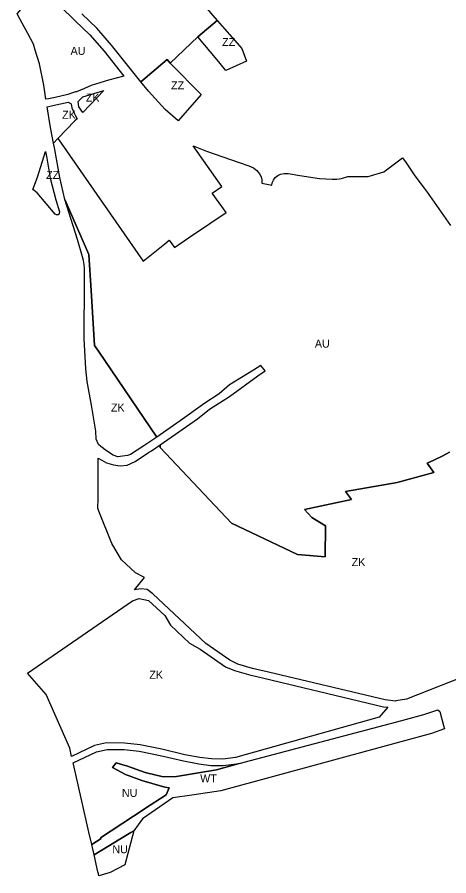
# Model space of a CAD drawing. Extents: x -535894 to -532834, y -1165802 to -1163647.
# Drawn here: x -535156 to -534886, y -1165663 to -1165127 of the extents above; entities that cross this region are included whole.
import ezdxf

# ---------------------------------------------------------------- set-up
doc = ezdxf.new("R2010")
doc.units = 0
for name, color, linetype in [('Vrstva 10', 7, 'Continuous'), ('Vrstva 16', 7, 'Continuous'), ('Vrstva 19', 7, 'Continuous'), ('Vrstva 22', 7, 'Continuous'), ('Vrstva 4', 7, 'Continuous')]:
    doc.layers.add(name, color=color, linetype=linetype)

msp = doc.modelspace()

# ---------------------------------------------------------------- linework, layer by layer
at = {"layer": 'Vrstva 10'}
for points in [[(-535030.794, -1165128.551), (-535016.81, -1165144.52), (-535015.48, -1165146.04), (-535012.56, -1165153.94), (-535025.48, -1165159.77), (-535026.15, -1165158.85), (-535030.91, -1165153.2), (-535042.84, -1165138.9)], [(-535078.389, -1165167.024), (-535062.12, -1165153.01), (-535060.13, -1165155.29), (-535059.81, -1165155.66), (-535040.74, -1165174.89), (-535055.086, -1165191.249), (-535063.193, -1165184.14), (-535073.739, -1165172.685)], [(-535145.859, -1165234.181), (-535143.033, -1165226.447), (-535137.971, -1165210.486), (-535137.13, -1165214.5), (-535134.967, -1165227.138), (-535131.592, -1165240.499), (-535129.335, -1165248.149), (-535129.389, -1165249.15), (-535130.061, -1165249.893), (-535131.052, -1165250.047), (-535131.919, -1165249.542), (-535143.165, -1165236.25)]]:
    msp.add_lwpolyline(points, close=True, dxfattribs=at)
at = {"layer": 'Vrstva 16'}
for points in [[(-535114.67, -1165186.14), (-535117.077, -1165182.508), (-535117.507, -1165179.149), (-535114.59, -1165176.22), (-535101.55, -1165172.42)], [(-535118.3, -1165189.93), (-535119.57, -1165191.26), (-535130.24, -1165202.4), (-535132.906, -1165205.189), (-535134.644, -1165196.443), (-535135.082, -1165194.239), (-535136.921, -1165182.604), (-535133.443, -1165181.633), (-535123.795, -1165179.535), (-535121.98, -1165180.725), (-535121.499, -1165183.162), (-535119.975, -1165186.84), (-535119.491, -1165187.733)], [(-535125.87, -1165240.38), (-535110.91, -1165274.78), (-535109.49, -1165297.17), (-535107.33, -1165331.56), (-535104.88, -1165335.18), (-535068.421, -1165388.794), (-535076.515, -1165394.257), (-535084.898, -1165399.647), (-535086.711, -1165400.218), (-535089.815, -1165400.622), (-535092.83, -1165401.015), (-535095.698, -1165400.055), (-535099.891, -1165397.3), (-535103.387, -1165394.572), (-535104.973, -1165393.334), (-535106.384, -1165390.083), (-535106.611, -1165385.025), (-535109.318, -1165368.871), (-535111.891, -1165354.083), (-535112.849, -1165346.141), (-535113.849, -1165327.11), (-535113.63, -1165291.112), (-535113.598, -1165285.864), (-535113.669, -1165283.44), (-535113.917, -1165280.968), (-535114.34, -1165278.52), (-535114.922, -1165276.165), (-535117.999, -1165265.365)], [(-535149.25, -1165536.15), (-535083.65, -1165491.01), (-535079.48, -1165489.46), (-535073.7, -1165490.85), (-535063.55, -1165500.03), (-535059.98, -1165506.16), (-535048.04, -1165517.37), (-535041.43, -1165521.13), (-535025.58, -1165532.21), (-535020.09, -1165534.38), (-535009.77, -1165537.3), (-535006.933, -1165537.976), (-534926.87, -1165557.06), (-534924.332, -1165557.424), (-534929.63, -1165563.61), (-535019.35, -1165588.86), (-535027.27, -1165589.76), (-535034.45, -1165589.68), (-535041.62, -1165588.86), (-535051.02, -1165587.04), (-535065.45, -1165583.66), (-535078.98, -1165580.85), (-535088.71, -1165579.86), (-535099.93, -1165579.7), (-535107.35, -1165581.35), (-535121.655, -1165588.062), (-535122.82, -1165582.96), (-535137.55, -1165549.48)]]:
    msp.add_lwpolyline(points, close=True, dxfattribs=at)
msp.add_lwpolyline([(-534877.24, -1165538.36), (-534912.68, -1165552.42), (-534919.2, -1165553.5), (-534919.44, -1165553.53), (-534926.03, -1165552.84), (-534998.84, -1165535.55), (-535008.78, -1165533.19), (-535017.91, -1165530.5), (-535022.95, -1165527.99), (-535037.98, -1165517.6), (-535070.93, -1165486.65), (-535074.543, -1165483.89), (-535078.527, -1165483.386), (-535082.4, -1165484.03), (-535076.26, -1165476.34), (-535081.822, -1165473.417), (-535090.626, -1165465.393), (-535096.666, -1165455.119), (-535104.637, -1165435.067), (-535105.398, -1165433.153), (-535105.08, -1165427.18), (-535105, -1165401.823), (-535102.855, -1165403.084), (-535099.848, -1165404.852), (-535095.444, -1165405.995), (-535091.323, -1165406.681), (-535087.093, -1165406.349), (-535081.996, -1165403.907), (-535073.648, -1165398.418), (-535071.799, -1165397.236), (-535066.459, -1165393.597), (-535066.38, -1165395.21), (-535021.86, -1165442.54), (-534980.62, -1165462.08), (-534963.38, -1165463.4), (-534963.24, -1165444.04), (-534971.78, -1165438.88), (-534976.33, -1165433.85), (-534946.88, -1165427.7), (-534950.64, -1165422.73), (-534918.48, -1165416.99), (-534895.63, -1165410.85), (-534899.67, -1165405.03), (-534895.49, -1165403.09), (-534889.94, -1165400.51), (-534885.71, -1165398.12)], dxfattribs=at)
at = {"layer": 'Vrstva 19'}
for points in [[(-535103.18, -1165639.32), (-535109.1, -1165643.08), (-535110.85, -1165635.43), (-535120.55, -1165592.9), (-535120.744, -1165592.052), (-535106.051, -1165585.159), (-535099.519, -1165583.706), (-535088.941, -1165583.857), (-535079.591, -1165584.808), (-535066.313, -1165587.566), (-535051.857, -1165590.952), (-535042.228, -1165592.817), (-535034.7, -1165593.677), (-535027.066, -1165593.763), (-535017.005, -1165592.619), (-535031.28, -1165596.42), (-535056.11, -1165600.58), (-535064.42, -1165600.94), (-535075.77, -1165598.23), (-535086.71, -1165594.09), (-535093.94, -1165592.1), (-535096.22, -1165595.01), (-535088.09, -1165599.33), (-535077.76, -1165603.24), (-535063.44, -1165607.34), (-535060.83, -1165607.77), (-535062.6, -1165612.04), (-535076.16, -1165620.93), (-535076.36, -1165621.07), (-535103.74, -1165639.03)], [(-535082.82, -1165634.47), (-535088.47, -1165655.7), (-535097.63, -1165660.52), (-535104.63, -1165662.66), (-535104.92, -1165661.39), (-535105.21, -1165660.12), (-535107.61, -1165649.63), (-535086.73, -1165636.86), (-535084.78, -1165635.66)]]:
    msp.add_lwpolyline(points, close=True, dxfattribs=at)
at = {"layer": 'Vrstva 22'}
msp.add_lwpolyline([(-535141.331, -1165107.067), (-535128.931, -1165119.482), (-535119.396, -1165128.806), (-535110.216, -1165137.551), (-535101.402, -1165147.865), (-535089.002, -1165163.415), (-535098.68, -1165165.83), (-535109.532, -1165169.282), (-535113.551, -1165171.039), (-535118.727, -1165173.09), (-535119.161, -1165173.236), (-535120.442, -1165173.67), (-535124.139, -1165174.765), (-535131.907, -1165176.691), (-535136.049, -1165177.441), (-535137.699, -1165177.679), (-535139.073, -1165168.99), (-535141.761, -1165155.672), (-535144.388, -1165147.195), (-535145.543, -1165143.469), (-535148.99, -1165136.793), (-535152.58, -1165130.217), (-535155.665, -1165124.565), (-535141.94, -1165107.81)], close=True, dxfattribs=at)
for points in [[(-535041.39, -1165116.45), (-535030.794, -1165128.551), (-535042.84, -1165138.9), (-535060.13, -1165155.29), (-535062.12, -1165153.01), (-535078.389, -1165167.024), (-535096.773, -1165144.045), (-535105.854, -1165133.419), (-535115.229, -1165124.489)], [(-534885.71, -1165398.12), (-534889.94, -1165400.51), (-534895.49, -1165403.09), (-534899.67, -1165405.03), (-534895.63, -1165410.85), (-534918.48, -1165416.99), (-534950.64, -1165422.73), (-534946.88, -1165427.7), (-534976.33, -1165433.85), (-534971.78, -1165438.88), (-534963.24, -1165444.04), (-534963.38, -1165463.4), (-534980.62, -1165462.08), (-535021.86, -1165442.54), (-535066.38, -1165395.21), (-535066.459, -1165393.597), (-535043.045, -1165377.297), (-535035.57, -1165371.22), (-535023.047, -1165363.292), (-535005.398, -1165350.5), (-535000.94, -1165347.399), (-535003.447, -1165343.979), (-535008.17, -1165346.93), (-535023.08, -1165356.13), (-535029.62, -1165361.786), (-535038.579, -1165367.539), (-535053.883, -1165378.489), (-535068.421, -1165388.794), (-535104.88, -1165335.18), (-535107.33, -1165331.56), (-535109.49, -1165297.17), (-535110.91, -1165274.78), (-535125.87, -1165240.38), (-535128.956, -1165226.673), (-535132.101, -1165209.239), (-535132.906, -1165205.189), (-535130.24, -1165202.4), (-535128.27, -1165205.23), (-535076.93, -1165278.88), (-535063.56, -1165267.97), (-535060.717, -1165265.884), (-535057.475, -1165270.304), (-535048.691, -1165264.377), (-535035.415, -1165255.418), (-535025.139, -1165248.484), (-535033.85, -1165236.42), (-535027.81, -1165232.2), (-535045.87, -1165206.9), (-535037.55, -1165210.25), (-535017.131, -1165217.289), (-535010.939, -1165219.424), (-535008.151, -1165220.618), (-535005.995, -1165222.244), (-535004.369, -1165224.4), (-535003.441, -1165226.232), (-535002.91, -1165228.216), (-535002.864, -1165230.269), (-534996.705, -1165231.467), (-534996.421, -1165230.007), (-534995.639, -1165228.234), (-534994.498, -1165226.668), (-534992.956, -1165225.495), (-534991.219, -1165224.637), (-534988.908, -1165224.168), (-534986.553, -1165224.068), (-534979.286, -1165225.462), (-534966.878, -1165227.187), (-534959.082, -1165227.751), (-534956.161, -1165227.718), (-534953.275, -1165227.27), (-534949.227, -1165225.98), (-534936.53, -1165225.98), (-534926.75, -1165223.13), (-534915.11, -1165214.3), (-534912.87, -1165217.53), (-534907.36, -1165225.52), (-534901.67, -1165233.4), (-534899.65, -1165235.85), (-534885.09, -1165256.54)]]:
    msp.add_lwpolyline(points, dxfattribs=at)
at = {"layer": 'Vrstva 4'}
msp.add_lwpolyline([(-534901.88, -1165561.94), (-534893.04, -1165558.98), (-534891.75, -1165560.02), (-534889.42, -1165568.74), (-534888.88, -1165570.88), (-534897.05, -1165573.8), (-535028.46, -1165609.66), (-535046.55, -1165612.31), (-535058.4, -1165614.04), (-535077.5, -1165627.02), (-535082.82, -1165634.47), (-535084.78, -1165635.66), (-535086.73, -1165636.86), (-535107.61, -1165649.63), (-535109.1, -1165643.08), (-535103.18, -1165639.32), (-535103.74, -1165639.03), (-535076.36, -1165621.07), (-535076.16, -1165620.93), (-535062.6, -1165612.04), (-535060.83, -1165607.77), (-535063.44, -1165607.34), (-535077.76, -1165603.24), (-535088.09, -1165599.33), (-535096.22, -1165595.01), (-535093.94, -1165592.1), (-535086.71, -1165594.09), (-535075.77, -1165598.23), (-535064.42, -1165600.94), (-535056.11, -1165600.58), (-535031.28, -1165596.42), (-535017.005, -1165592.619), (-534915.56, -1165565.61)], close=True, dxfattribs=at)

# ---------------------------------------------------------------- texts
at = {"layer": 'Vrstva 10'}
for p in [(-535027.7, -1165144.5472), (-535059.5645, -1165171.6147), (-535137.597, -1165227.551)]:
    msp.add_text('ZZ', height=5, rotation=360, dxfattribs=at).set_placement(p)
at = {"layer": 'Vrstva 16'}
for rotation, p in [(360, (-535112.8001, -1165179.28)), (0, (-535127.6105, -1165190.0097)), (0, (-535097.1455, -1165372.8289)), (360, (-534946.8191, -1165469.27)), (0, (-535073.1455, -1165539.61))]:
    msp.add_text('ZK', height=5, rotation=rotation, dxfattribs=at).set_placement(p)
at = {"layer": 'Vrstva 19'}
for rotation, p in [(360, (-535090.2699, -1165613.393)), (0, (-535096.2199, -1165648.565))]:
    msp.add_text('NU', height=5, rotation=rotation, dxfattribs=at).set_placement(p)
at = {"layer": 'Vrstva 22'}
for p in [(-535122.3335, -1165150.0819), (-534969.8246, -1165332.9)]:
    msp.add_text('AU', height=5, rotation=0, dxfattribs=at).set_placement(p)
at = {"layer": 'Vrstva 4'}
msp.add_text('WT', height=5, rotation=360, dxfattribs=at).set_placement((-535041.4384, -1165604.305))

doc.saveas('drawing.dxf')
